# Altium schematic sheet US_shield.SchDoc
size A4; Date: 09 July 2012; Author: Simon Markham; DrawnBy: Simon Markham; Engineer: Simon Markham; Organization: Markham Designs
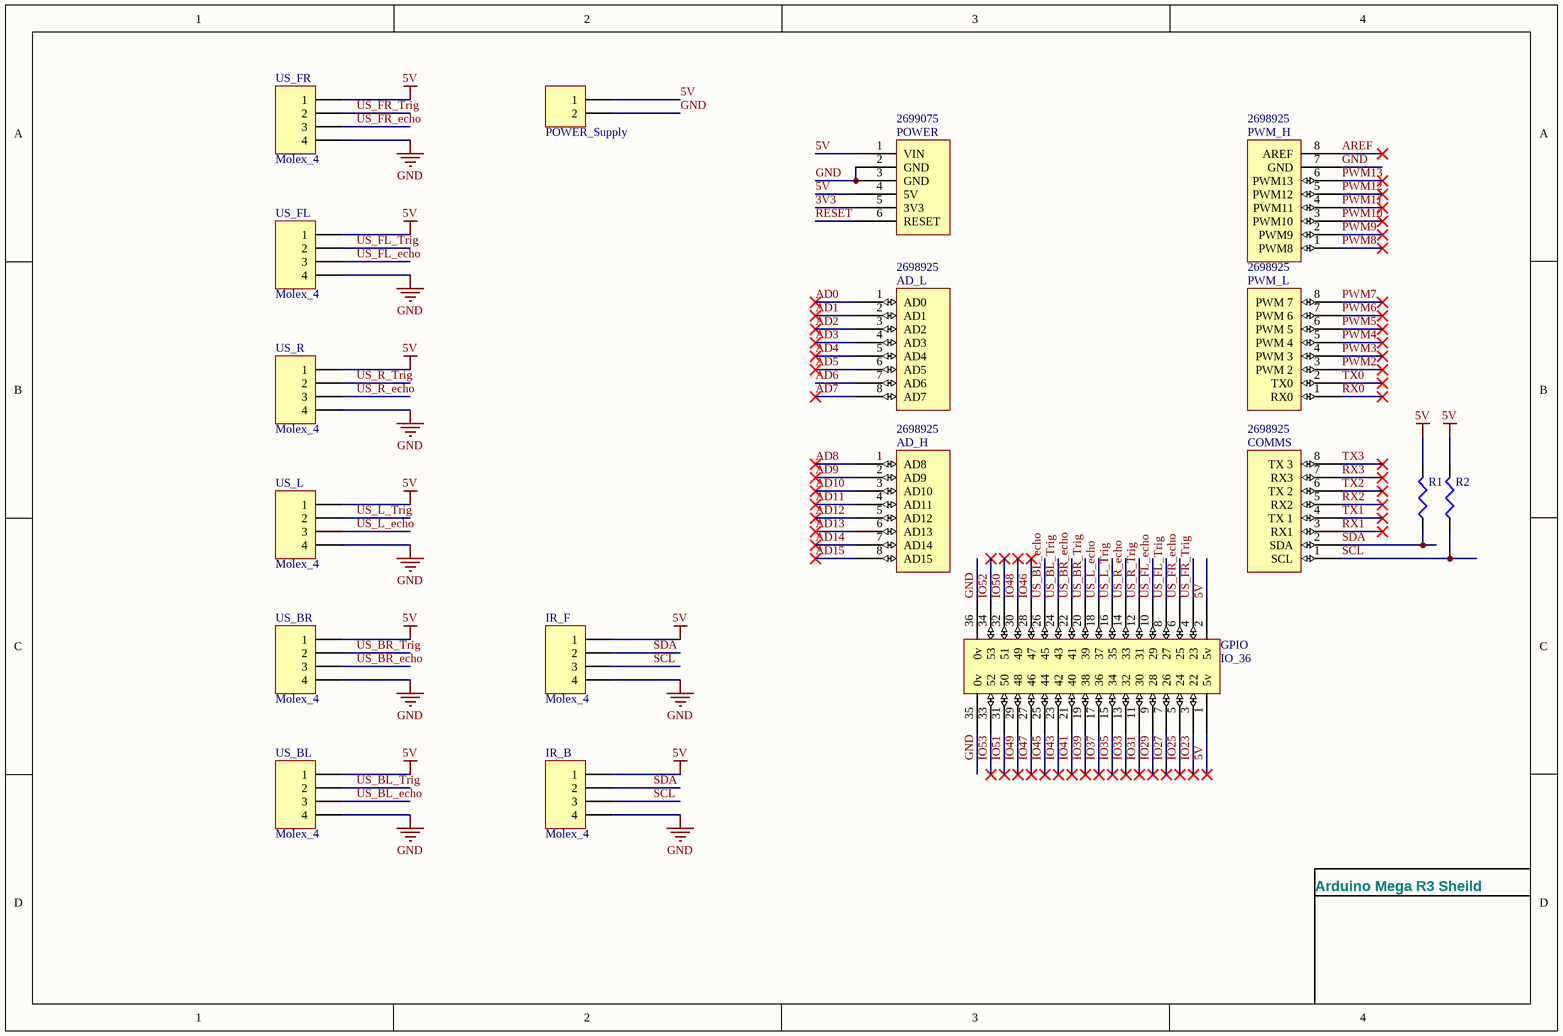
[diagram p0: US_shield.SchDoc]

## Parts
AD_H  Supplier Part Number 4: 2698925  [Header 8x1 8.5mm]  (hidden comment: AD_H)
AD_L  Supplier Part Number 5: 2698925  [Header 8x1 8.5mm]  (hidden comment: AD_L)
COMMS  Supplier Part Number 4: 2698925  [Header 8x1 8.5mm]  (hidden comment: Communication)
GPIO  IO_36  [HEADER 36X 8MM]
IR_B  Molex_4  [Header4_ecam]
IR_F  Molex_4  [Header4_ecam]
POWER  Supplier Part Number 2: 2699075  [Header 6x1 8.5mm]  (hidden comment: POWER)
POWER_Supply  Molex_2  [Header_2Ecam]  (value not drawn)
PWM_H  Supplier Part Number 4: 2698925  [Header 8x1 8.5mm]  (hidden comment: PWM_H)
PWM_L  Supplier Part Number 4: 2698925  [Header 8x1 8.5mm]  (hidden comment: PWM_L)
R1  Résistance  [AXIAL-0.4]  (value not drawn)
R2  Résistance  [AXIAL-0.4]  (value not drawn)
US_BL  Molex_4  [Header4_ecam]
US_BR  Molex_4  [Header4_ecam]
US_FL  Molex_4  [Header4_ecam]
US_FR  Molex_4  [Header4_ecam]
US_L  Molex_4  [Header4_ecam]
US_R  Molex_4  [Header4_ecam]

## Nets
5V: GPIO.1(5v) GPIO.2(5v) IR_B.1 IR_F.1 POWER.1(VIN) POWER.4(5V) POWER_Supply.1 R1.2 R2.2 US_BL.1 US_BR.1 US_FL.1 US_FR.1 US_L.1 US_R.1
GND: GPIO.35(0v) GPIO.36(0v) IR_B.4 IR_F.4 POWER.2(GND) POWER.3(GND) POWER_Supply.2 PWM_H.7(GND) US_BL.4 US_BR.4 US_FL.4 US_FR.4 US_L.4 US_R.4
3V3: POWER.5(3V3)
AD0: AD_L.1(AD0)
AD1: AD_L.2(AD1)
AD2: AD_L.3(AD2)
AD3: AD_L.4(AD3)
AD4: AD_L.5(AD4)
AD5: AD_L.6(AD5)
AD6: AD_L.7(AD6)
AD7: AD_L.8(AD7)
AD8: AD_H.1(AD8)
AD9: AD_H.2(AD9)
AD10: AD_H.3(AD10)
AD11: AD_H.4(AD11)
AD12: AD_H.5(AD12)
AD13: AD_H.6(AD13)
AD14: AD_H.7(AD14)
AD15: AD_H.8(AD15)
AREF: PWM_H.8(AREF)
IO23: GPIO.3(22)
IO25: GPIO.5(24)
IO27: GPIO.7(26)
IO29: GPIO.9(28)
IO31: GPIO.11(30)
IO33: GPIO.13(32)
IO35: GPIO.15(34)
IO37: GPIO.17(36)
IO39: GPIO.19(38)
IO41: GPIO.21(40)
IO43: GPIO.23(42)
IO45: GPIO.25(44)
IO46: GPIO.28(47)
IO47: GPIO.27(46)
IO48: GPIO.30(49)
IO49: GPIO.29(48)
IO50: GPIO.32(51)
IO51: GPIO.31(50)
IO52: GPIO.34(53)
IO53: GPIO.33(52)
PWM2: PWM_L.3(PWM_2)
PWM3: PWM_L.4(PWM_3)
PWM4: PWM_L.5(PWM_4)
PWM5: PWM_L.6(PWM_5)
PWM6: PWM_L.7(PWM_6)
PWM7: PWM_L.8(PWM_7)
PWM8: PWM_H.1(PWM8)
PWM9: PWM_H.2(PWM9)
PWM10: PWM_H.3(PWM10)
PWM11: PWM_H.4(PWM11)
PWM12: PWM_H.5(PWM12)
PWM13: PWM_H.6(PWM13)
RESET: POWER.6(RESET)
RX0: PWM_L.1(RX0)
RX1: COMMS.3(RX1)
RX2: COMMS.5(RX2)
RX3: COMMS.7(RX3)
SCL: COMMS.1(SCL) IR_B.3 IR_F.3 R2.1
SDA: COMMS.2(SDA) IR_B.2 IR_F.2 R1.1
TX0: PWM_L.2(TX0)
TX1: COMMS.4(TX_1)
TX2: COMMS.6(TX_2)
TX3: COMMS.8(TX_3)
US_BL_echo: GPIO.26(45) US_BL.3
US_BL_Trig: GPIO.24(43) US_BL.2
US_BR_echo: GPIO.22(41) US_BR.3
US_BR_Trig: GPIO.20(39) US_BR.2
US_FL_echo: GPIO.10(29) US_FL.3
US_FL_Trig: GPIO.8(27) US_FL.2
US_FR_echo: GPIO.6(25) US_FR.3
US_FR_Trig: GPIO.4(23) US_FR.2
US_L_echo: GPIO.18(37) US_L.3
US_L_Trig: GPIO.16(35) US_L.2
US_R_echo: GPIO.14(33) US_R.3
US_R_Trig: GPIO.12(31) US_R.2

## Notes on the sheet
- Arduino Mega R3 Sheild

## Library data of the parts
GPIO = IO_36: Header, 36-Pin
IR_B IR_F US_BL US_BR US_FL US_FR US_L US_R = Molex_4: Header, 4-Pin
POWER_Supply = Molex_2: Header, 2-pin
R1 R2 = Résistance: Résistance standard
